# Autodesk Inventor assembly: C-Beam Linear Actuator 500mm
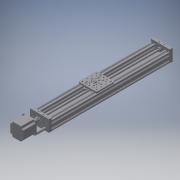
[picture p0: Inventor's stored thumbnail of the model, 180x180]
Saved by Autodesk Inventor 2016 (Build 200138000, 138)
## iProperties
Created: 2015-08
Part Number: C-Beam Linear Actuator 500mm
Description: STEP AP203
Document SubType Name: Assembly
Designer: John
Sending System: SolidWorks 2014
Preprocessor: SwSTEP 2.0
Title: C-Beam Linear Actuator 500mm.step
Revision Number: ANY
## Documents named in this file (19)
- D:\3D Printer Designs\John Ledden Designs\DLP Printer\STEP Parts Library 1.1\Assemblies\C-Beam Linear Actuator\C-Beam Linear Actuator 500mm.iam
- D:\3D Printer Designs\John Ledden Designs\DLP Printer\STEP Parts Library 1.1\Assemblies\C-Beam Linear Actuator\Low Profile Screw M5_M5 x 20.ipt
- D:\3D Printer Designs\John Ledden Designs\DLP Printer\STEP Parts Library 1.1\Assemblies\C-Beam Linear Actuator\Nylon Insert Lock Nut M5.ipt
- D:\3D Printer Designs\John Ledden Designs\DLP Printer\STEP Parts Library 1.1\Assemblies\C-Beam Linear Actuator\Low Profile Screw M5_M5 x 25.ipt
- D:\3D Printer Designs\John Ledden Designs\DLP Printer\STEP Parts Library 1.1\Assemblies\C-Beam Linear Actuator\Low Profile Screw M5_M5 x 55.ipt
- D:\3D Printer Designs\John Ledden Designs\DLP Printer\STEP Parts Library 1.1\Assemblies\C-Beam Linear Actuator\C-Beam End Mount.ipt
- D:\3D Printer Designs\John Ledden Designs\DLP Printer\STEP Parts Library 1.1\Assemblies\C-Beam Linear Actuator\C-Beam 40x80x500 Linear Rail.ipt
- D:\3D Printer Designs\John Ledden Designs\DLP Printer\STEP Parts Library 1.1\Assemblies\C-Beam Linear Actuator\Ball Bearing 8 x 16 x 5.ipt
- D:\3D Printer Designs\John Ledden Designs\DLP Printer\STEP Parts Library 1.1\Assemblies\C-Beam Linear Actuator\Shim Washer 8mm.ipt
- D:\3D Printer Designs\John Ledden Designs\DLP Printer\STEP Parts Library 1.1\Assemblies\C-Beam Linear Actuator\Lock Collar 8mm.ipt
- D:\3D Printer Designs\John Ledden Designs\DLP Printer\STEP Parts Library 1.1\Assemblies\C-Beam Linear Actuator\Aluminum Spacer 40mm.ipt
- D:\3D Printer Designs\John Ledden Designs\DLP Printer\STEP Parts Library 1.1\Assemblies\C-Beam Linear Actuator\Nema 23 Stepper Motor.ipt
- D:\3D Printer Designs\John Ledden Designs\DLP Printer\STEP Parts Library 1.1\Assemblies\C-Beam Linear Actuator\Flexible Coupling 0.25in x 8mm.ipt
- D:\3D Printer Designs\John Ledden Designs\DLP Printer\STEP Parts Library 1.1\Assemblies\C-Beam Linear Actuator\8mm leadscrew 540mm.ipt
- D:\3D Printer Designs\John Ledden Designs\DLP Printer\STEP Parts Library 1.1\Assemblies\C-Beam Linear Actuator\C-Beam Gantry Plate.ipt
- D:\3D Printer Designs\John Ledden Designs\DLP Printer\STEP Parts Library 1.1\Assemblies\C-Beam Linear Actuator\8mm Acme Nut Block.ipt
- D:\3D Printer Designs\John Ledden Designs\DLP Printer\STEP Parts Library 1.1\Assemblies\C-Beam Linear Actuator\Xtreme Mini V Wheel_Straight.iam
- D:\3D Printer Designs\John Ledden Designs\DLP Printer\STEP Parts Library 1.1\Assemblies\C-Beam Linear Actuator\Xtreme Mini V Wheel_Eccentric.iam
- D:\3D Printer Designs\John Ledden Designs\DLP Printer\STEP Parts Library 1.1\Assemblies\C-Beam Linear Actuator\Aluminum Spacer 3mm.ipt
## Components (40 placed, 40 different names)
1. Low Profile Screw M5_M5 x 20_1
2. Low Profile Screw M5_M5 x 20_2
3. Low Profile Screw M5_M5 x 20_3
4. Low Profile Screw M5_M5 x 20_4
5. Low Profile Screw M5_M5 x 20_5
6. Low Profile Screw M5_M5 x 20_6
7. Low Profile Screw M5_M5 x 20_7
8. Low Profile Screw M5_M5 x 20_8
9. Nylon Insert Lock Nut M5_9
10. Nylon Insert Lock Nut M5_10
11. Low Profile Screw M5_M5 x 20_11
12. Low Profile Screw M5_M5 x 20_12
13. Low Profile Screw M5_M5 x 25_13
14. Low Profile Screw M5_M5 x 25_14
15. Low Profile Screw M5_M5 x 25_15
16. Low Profile Screw M5_M5 x 25_16
17. Low Profile Screw M5_M5 x 55_17
18. Low Profile Screw M5_M5 x 55_18
19. C-Beam End Mount_19
20. C-Beam 40x80x500 Linear Rail_20
21. C-Beam End Mount_21
22. Ball Bearing 8 x 16 x 5_22
23. Ball Bearing 8 x 16 x 5_23
24. Shim Washer 8mm_24
25. Shim Washer 8mm_25
26. Lock Collar 8mm_26
27. Lock Collar 8mm_27
28. Aluminum Spacer 40mm_28
29. Aluminum Spacer 40mm_29
30. Nema 23 Stepper Motor_30
31. Flexible Coupling 0.25in x 8mm_31
32. 8mm leadscrew 540mm_32
33. C-Beam Gantry Plate_33
34. 8mm Acme Nut Block_34
35. Xtreme Mini V Wheel_Straight_35 [sub-assembly]
36. Xtreme Mini V Wheel_Straight_36 [sub-assembly]
37. Xtreme Mini V Wheel_Eccentric_37 [sub-assembly]
38. Xtreme Mini V Wheel_Eccentric_38 [sub-assembly]
39. Aluminum Spacer 3mm_39
40. Aluminum Spacer 3mm_40
